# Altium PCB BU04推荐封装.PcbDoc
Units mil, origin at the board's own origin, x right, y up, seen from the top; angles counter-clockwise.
Board outline 6000 x 4000 mil, 2 copper layers (Top, Bottom), stack 12.7 mil thick; 1 components, 0 nets, 36 pads, 0 vias.
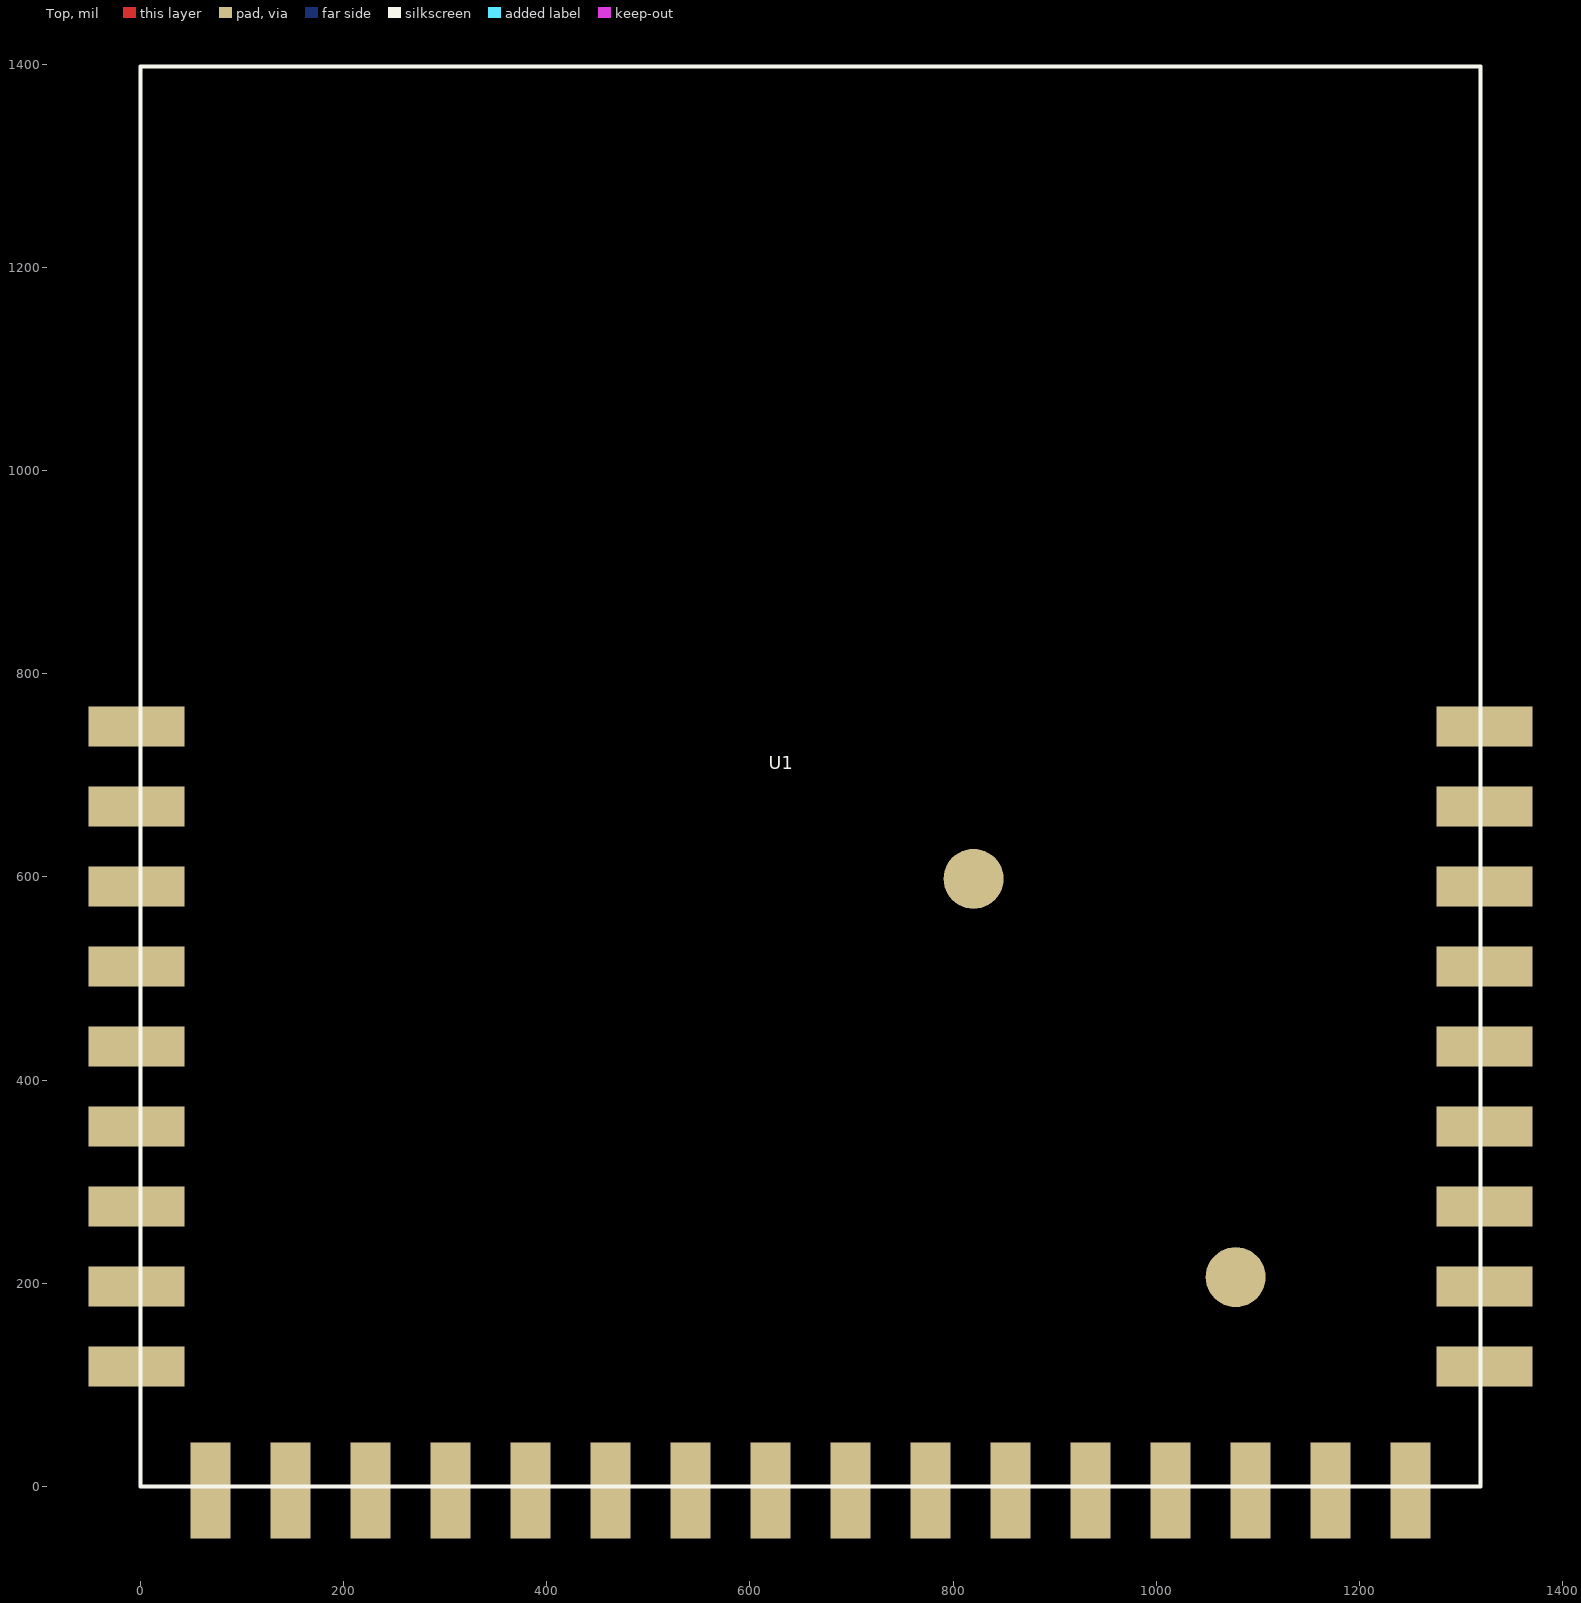
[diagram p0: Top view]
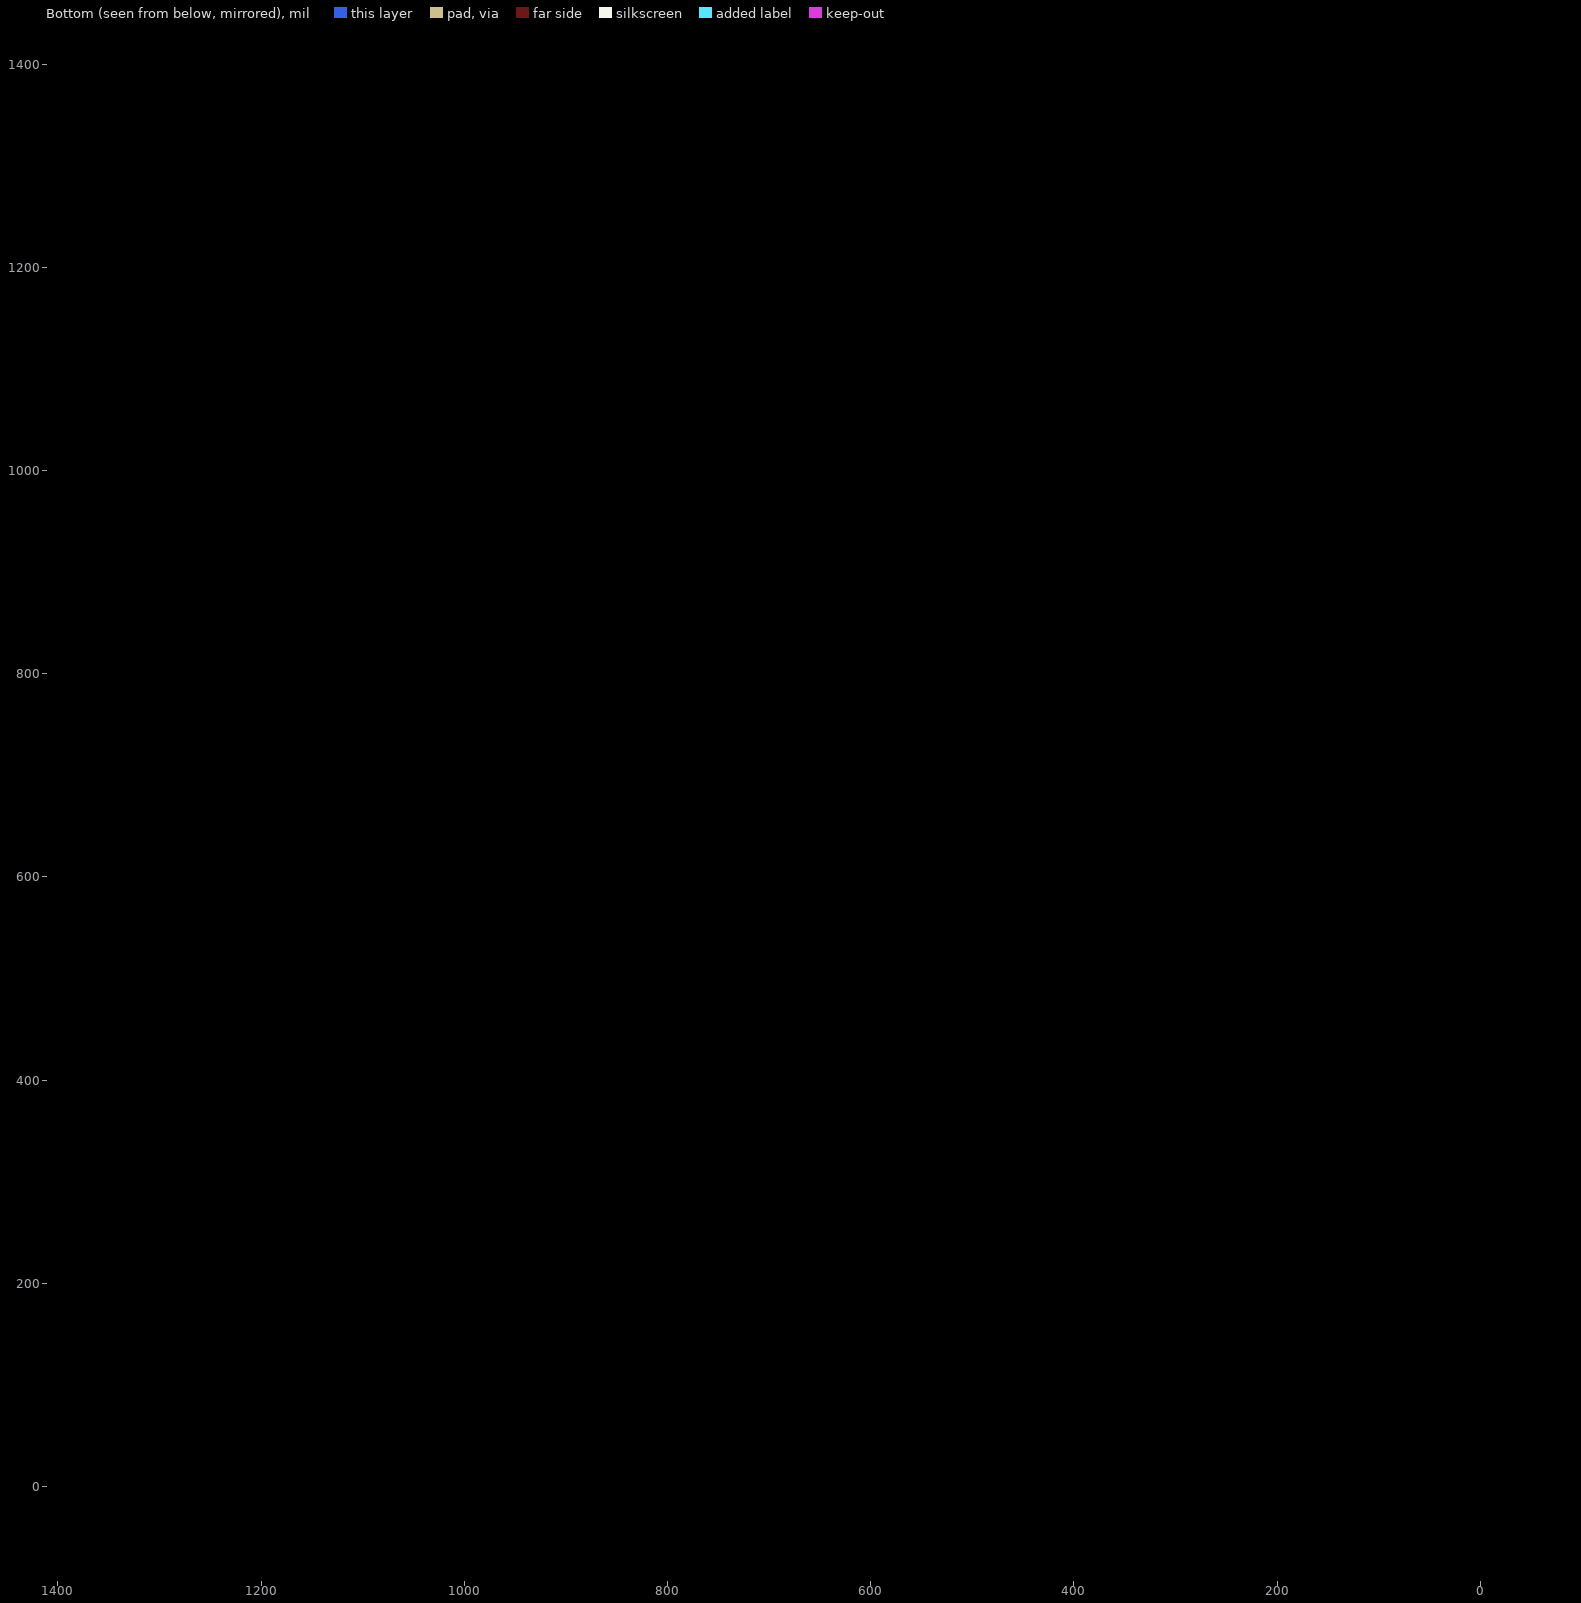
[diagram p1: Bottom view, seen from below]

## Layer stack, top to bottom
Solder Mask Top: solder mask 0.4, Solder Resist, Dk 3.5
Top: signal copper 1.35
Dielectric 1: dielectric 10, FR-4, Dk 4.3
Bottom: signal copper 1.35
Solder Mask Bottom: solder mask 0.4, Solder Resist, Dk 3.5

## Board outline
-9000,-9000 -3000,-9000 -3000,-5000 -9000,-5000

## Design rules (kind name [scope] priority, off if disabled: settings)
Clearance "Clearance - Default - DEFAULT- SMD" [IsVia vs IsSMTPin] p1: gap=6 ignorepadtopadclearanceinfootprint=FALSE
Clearance "Clearance - Default - DEFAULT - Via" [IsVia vs IsVia] p2: gap=6 ignorepadtopadclearanceinfootprint=FALSE
Clearance "Clearance - Default - DEFAULT - Net" [All] p3: gap=6 ignorepadtopadclearanceinfootprint=FALSE except(0: Arc-Hole Track-Hole SMDPad-Hole THPad-Hole Via-Hole Fill-Hole Poly-Hole Region-Hole Text-Hole; 10: Text-Text)
ComponentClearance "ComponentClearance - Default - DEFAULT" [All] p1: gap=6 collisioncheckmode=3 verticalgap=10 showdistances=FALSE
FanoutControl Fanout_Small [(CompPinCount < 5)] p3: bgadir=Out bgaviamode=Centered fanoutstyle=Auto fanoutdirection=OutThenIn viagrid=1 // Fanout_Small (Default Rule)
FanoutControl Fanout_SOIC [IsSOIC] p4: bgadir=Out bgaviamode=Centered fanoutstyle=Auto fanoutdirection=Alternating viagrid=1 // Fanout_SOIC (Default Rule)
HoleToHoleClearance "HoleToHoleClearance - Default - DEFAULT" [All] p1: gap=6 allowstackedmicrovias=TRUE
Length "Default Length" [All] p1: maxlimit=50000 minlimit=0
MaxMinImpedance "Default Impedance" [All] p1: minimum=50.00 maximum=150.0
ParallelSegment "Default Parallel Segment Adjasent" [All] p1: limit=1000 gap=200
ParallelSegment "Default Parallel Segment Same Layer" [All] p2: limit=1000 gap=200
PlaneConnect "Default PlaneConnect" [All] p1: planeconnectstyle=Relief reliefexpansion=20 reliefentries=4 reliefconductorwidth=15 reliefairgap=10
PolygonConnect "PolygonConnect - Default SMT" [IsSMTPin] p1: connectstyle=Relief reliefconductorwidth=10 reliefentries=4 polygonreliefangle="45 Angle" airgapwidth=10
PolygonConnect "PolygonConnect - Default Pad" [All] p2: connectstyle=Relief reliefconductorwidth=15 reliefentries=4 polygonreliefangle="45 Angle" airgapwidth=10
RoutingLayers "RoutingLayers - Default - DEFAULT" [All] p1: top layer_v5=TRUE bottom layer_v5=TRUE
RoutingPriority "RoutingPriority - Default - DEFAULT" [All] p1: routingpriority=3
RoutingTopology "Default Routing Topology" [All] p1: topology=Shortest
RoutingVias "RoutingVias - Default - DEFAULT" [All] p1: holewidth=37 width=55 viastyle="Through Hole" minholewidth=37 minwidth=55 maxholewidth=37 maxwidth=55
SMDToCorner "SMDToCorner - Default - DEFAULT" [All] p1: distance=60000
SolderMaskExpansion [All] p1: expansion=4
Width "Default Width" [All] p1: maxlimit=6 minlimit=6 preferedwidth=6
20 further rules are at their usual default settings.

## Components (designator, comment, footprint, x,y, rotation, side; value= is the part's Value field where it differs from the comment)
U1 "BU04_MODE-T" BU04_MODE-T 0,0 r0 top

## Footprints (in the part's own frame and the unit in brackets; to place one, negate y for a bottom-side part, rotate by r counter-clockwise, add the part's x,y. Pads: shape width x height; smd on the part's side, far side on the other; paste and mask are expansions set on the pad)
BU04_MODE-T [mm]
  rect 2.4x1 smd: 1(-0.1,19) 2(-0.1,17) 3(-0.1,15) 4(-0.1,13) 5(-0.1,11) 6(-0.1,9) 7(-0.1,7) 8(-0.1,5) 9(-0.1,3) 26(33.6,3) 27(33.6,5) 28(33.6,7) 29(33.6,9) 30(33.6,11) 31(33.6,13) 32(33.6,15) 33(33.6,17) 34(33.6,19)
  rect 1x2.4 smd: 10(1.75,-0.1) 11(3.75,-0.1) 12(5.75,-0.1) 13(7.75,-0.1) 14(9.75,-0.1) 15(11.75,-0.1) 16(13.75,-0.1) 17(15.75,-0.1) 18(17.75,-0.1) 19(19.75,-0.1) 20(21.75,-0.1) 21(23.75,-0.1) 22(25.75,-0.1) 23(27.75,-0.1) 24(29.75,-0.1) 25(31.75,-0.1)
  round 1.5 smd: 35(20.828,15.189) 36(27.381,5.232)
  silkscreen extent 0,0 33.5,35.5

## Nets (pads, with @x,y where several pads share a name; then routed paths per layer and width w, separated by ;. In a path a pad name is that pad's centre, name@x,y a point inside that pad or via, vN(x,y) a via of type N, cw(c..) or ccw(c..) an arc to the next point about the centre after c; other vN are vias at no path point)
pads on no net: U1.1 U1.2 U1.3 U1.4 U1.5 U1.6 U1.7 U1.8 U1.9 U1.10 U1.11 U1.12 U1.13 U1.14 U1.15 U1.16 U1.17 U1.18 U1.19 U1.20 U1.21 U1.22 U1.23 U1.24 U1.25 U1.26 U1.27 U1.28 U1.29 U1.30 U1.31 U1.32 U1.33 U1.34 U1.35 U1.36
